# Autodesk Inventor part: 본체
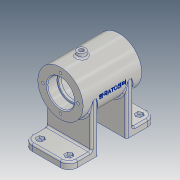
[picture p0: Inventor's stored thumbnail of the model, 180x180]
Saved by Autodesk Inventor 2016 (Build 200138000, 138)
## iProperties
Created: 2017-02
Part Number: 본체
Material: 알루미늄 6061
Document SubType Name: Modeling
Designer: CAMTIC
Density: 2.7 g/cm^3
Appearance: 알루미늄 - 평지
Mass: 355.336 g
Surface Area: 422.271 cm^2
Volume: 131.606 cm^3
Author: CAMTIC
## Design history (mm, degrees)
sketch "스케치1"
  geometry: L1 (-35, 27)-(35, 27); L2 (35, 27)-(35, 0); L3 (35, 0)-(-35, 0); L4 (-35, 0)-(-35, 27); L5 (-52, -52)-(52, -52); L6 (52, -52)-(52, -60); L7 (52, -60)-(-52, -60); L8 (-52, -60)-(-52, -52); L9 (-25, 0)-(-17, 0); L10 (-17, 0)-(-17, -52); L11 (-17, -52)-(-25, -52); L12 (-25, -52)-(-25, 0); L13 (17, 0)-(25, 0); L14 (25, 0)-(25, -52); L15 (25, -52)-(17, -52); L16 (17, -52)-(17, 0); L17 (0, -77.4)-(0, 44.4) reference; 3 further points
  constraints: 32 end point, 8 parallel, 4 horizontal, 4 perpendicular, 2 collinear, 2 midpoint, 2 point on line, 1 coincident, 1 vertical alignment
  dimensions: "d0" = 54 diameter of L1 L3; "d1" = 70 distance between parallel lines of L2 L4; "d2" = 8 distance of L5.end L6.end; "d3" = 104 distance of L6.end L7.end; "d4" = 60 distance from line of L3.end L7; "d5" = 8 distance of L9.start L9.end; "d6" = 8 distance of L13.start L13.end; "d7" = 17 distance from line of point (0, -52) L10; "d8" = 17 distance between parallel lines of L16 L17
revolve "회전1" stored, may be unused: angle "d9" = 90 deg
extrude "돌출1" join sketch "스케치1" stored distance "d10" = 54; taper "d12" = 0 deg; dims "d11" = 5, "d13" = 0
extrude "돌출2" join sketch "스케치1" stored distance "d14" = 54; taper "d15" = 0 deg
sketch "스케치2"
  geometry: L1 (-17, -34.654)-(17, -34.654); L2 (17, -34.654)-(17, -60); L3 (17, -60)-(-17, -60); L4 (-17, -60)-(-17, -34.654); L5 (-35, -27)-(35, -27) reference; L6 (-17, -52)-(-17, 0) reference; L7 (17, 0)-(17, -52) reference; L8 (-52, -60)-(52, -60) reference; 1 further point
  constraints: 8 end point, 3 collinear, 2 parallel, 1 horizontal, 1 perpendicular
  dimensions: "d16" = 25.34558 distance between parallel lines of L3 L1
extrude "돌출3" cut sketch "스케치2" stored distance "d17" = 54; taper "d18" = 0 deg
node "작업 평면1"
sketch "스케치3"
  geometry: L1 (52, -27)-(52, 27) reference; L2 (35, 27)-(35, -27) reference; C1 r 5 at (10, 0); 1 further point
  constraints: 1 centre point, 1 horizontal alignment
  dimensions: "d20" = 10 diameter of C1; "d24" = 25 distance from line of C1.centre L2
extrude "돌출4" join sketch "스케치3" stored distance "d22" = 54; taper "d23" = 0 deg
sketch "스케치4"
  geometry: L1 (-35, -27)-(-35, 27) reference; L2 (-35, 0)-(-23, 0); L3 (-23, 0)-(-23, 16); L4 (-23, 16)-(-35, 16); L5 (-35, 16)-(-35, 0); L6 (-23, 0)-(-20, 0); L7 (-20, 0)-(-20, 14); L8 (-20, 14)-(-23, 14); L9 (-23, 14)-(-23, 0); L10 (-20, 0)-(20, 0); L11 (20, 0)-(20, 22); L12 (20, 22)-(-20, 22); L13 (-20, 22)-(-20, 0); L14 (20, 0)-(23, 0); L15 (23, 0)-(23, 14); L16 (23, 14)-(20, 14); L17 (20, 14)-(20, 0); L18 (23, 0)-(35, 0); L19 (35, 0)-(35, 16); L20 (35, 16)-(23, 16); L21 (23, 16)-(23, 0); L22 (35, -27)-(35, 27) reference; 1 further point
  constraints: 40 end point, 10 parallel, 5 horizontal, 5 perpendicular, 1 collinear, 1 midpoint
  dimensions: "d25" = 12 distance of L3.end L4.end; "d26" = 3 distance of L7.end L8.end; "d27" = 3 distance of L15.end L16.end (= d26); "d28" = 12 distance of L19.end L20.end (= d25); "d29" = 32 diameter of L4 L2; "d30" = 28 diameter of L8 L6; "d31" = 44 diameter of L12 L10; "d32" = 28 diameter of L16 L14; "d33" = 32 diameter of L20 L18
revolve "회전2" sketch "스케치4" stored, may be unused: angle "d34" = 90 deg
fillet "모깎기1" dims "d35" = 3
fillet "모깎기2" dims "d36" = 0.3
chamfer "모따기1" distance "d37" = 1; stored, may be unused: second distance "d38" = 2, angle "d39" = 45 deg
sketch "스케치5"
  geometry: C1 r 5 at (0, 0) reference; 1 further point
hole "구멍1" sketch "스케치5" at (0, 0) diameter "d40" = 5.188; stored, may be unused: countersink angle "d44" = 90 deg, drill point angle "d46" = 0 deg; dims "d41" = 12, "d42" = 4, "d43" = 2, "d45" = 16
fillet "모깎기3" dims "d47" = 2
sketch "스케치6"
  geometry: L1 (0, 0)-(-25.16, -16.339); L2 (0, 0)-(-44.384, 0); C1 r 14 at (0, 0) reference; 1 further point
  constraints: 4 end point, 1 horizontal
  dimensions: "d48" = 30 distance of L1.start L1.end; "d49" = 33 deg angle of L1 L2
node "작업 평면2"
sketch "스케치7"
  geometry: C1 r 6 at (0, 0); 1 further point
  constraints: 1 centre point, 1 coincident
  dimensions: "d50" = 12 diameter of C1
extrude "돌출5" join sketch "스케치7" stored distance "d51" = 54; taper "d52" = 0 deg
sketch "스케치8"
  geometry: C1 r 6 at (0, 0) reference; 2 further points
  constraints: 1 coincident
hole "구멍2" sketch "스케치8" at (0, 0), (0, 0) diameter "d53" = 5.188; stored, may be unused: countersink angle "d57" = 90 deg, drill point angle "d59" = 0 deg; dims "d54" = 12, "d55" = 4, "d56" = 2, "d58" = 16
fillet "모깎기4" dims "d60" = 2
sketch "스케치9" dims "d61" = 42
  geometry: L1 (0, 0)-(0, 21); C1 r 27 at (0, 0) reference; C2 r 14 at (0, 0) reference; 3 further points
  constraints: 2 coincident, 2 end point, 1 vertical, 1 vertical alignment, 2 other
hole "구멍3" sketch "스케치9" at (0, 21) diameter "d62" = 3.242; stored, may be unused: countersink angle "d66" = 90 deg, drill point angle "d68" = 118 deg; dims "d63" = 8, "d64" = 4, "d65" = 2, "d67" = 10
node "작업 평면4"
sketch "스케치10"
  geometry: L1 (-35, 27)-(35, 27) reference; L2 (-35, -27)-(-35, 27) reference; 2 further points
  constraints: 1 coincident, 1 other
  dimensions: "d73" = 27 distance from line of point (0, 0) L1; "d74" = 35 distance from line of point (0, 0) L2 (derived)
feature "엠보싱1" sketch "스케치10" dims "d12" = 0, "d75" = 0.5, "d76" = 0
fillet "모깎기5" dims "d77" = 10
sketch "스케치11"
  geometry: L1 (17, 54)-(-8, 54) reference; L2 (27, 10)-(27, 44) reference; L3 (-25, 64.9)-(-25, -11.401) reference; L4 (19.25, 47.897)-(21.5, 44); L5 (21.5, 44)-(19.25, 40.103); L6 (19.25, 40.103)-(14.75, 40.103); L7 (14.75, 40.103)-(12.5, 44); L8 (12.5, 44)-(14.75, 47.897); L9 (14.75, 47.897)-(19.25, 47.897); L10 (12.5, 44)-(21.5, 44); L11 (14.75, 40.103)-(19.25, 47.897); L12 (19.25, 40.103)-(14.75, 47.897); L13 (19.25, 13.897)-(21.5, 10); L14 (21.5, 10)-(19.25, 6.103); L15 (19.25, 6.103)-(14.75, 6.103); L16 (14.75, 6.103)-(12.5, 10); L17 (12.5, 10)-(14.75, 13.897); L18 (14.75, 13.897)-(19.25, 13.897); L19 (12.5, 10)-(21.5, 10); L20 (14.75, 6.103)-(19.25, 13.897); L21 (19.25, 6.103)-(14.75, 13.897); L22 (-64.75, 13.897)-(-62.5, 10); L23 (-62.5, 10)-(-64.75, 6.103); L24 (-64.75, 6.103)-(-69.25, 6.103); L25 (-69.25, 6.103)-(-71.5, 10); L26 (-71.5, 10)-(-69.25, 13.897); L27 (-69.25, 13.897)-(-64.75, 13.897); L28 (-71.5, 10)-(-62.5, 10); L29 (-69.25, 6.103)-(-64.75, 13.897); L30 (-64.75, 6.103)-(-69.25, 13.897); L31 (-64.75, 47.897)-(-62.5, 44); L32 (-62.5, 44)-(-64.75, 40.103); L33 (-64.75, 40.103)-(-69.25, 40.103); L34 (-69.25, 40.103)-(-71.5, 44); L35 (-71.5, 44)-(-69.25, 47.897); L36 (-69.25, 47.897)-(-64.75, 47.897); L37 (-71.5, 44)-(-62.5, 44); L38 (-69.25, 40.103)-(-64.75, 47.897); L39 (-64.75, 40.103)-(-69.25, 47.897); 16 further points
  constraints: 72 end point, 4 coincident, 4 horizontal, 4 midpoint, 2 symmetric about line, 1 vertical alignment, 52 other
  dimensions: "d78" = 34 distance of point (17, 10) point (17, 44); "d79" = 10 distance from line of L1 point (17, 44); "d80" = 10 distance from line of point (17, 44) L2; "d81" = 9 distance of L7.end L4.end; "d82" = 9 distance of L16.end L13.end; "d83" = 9 distance of L25.end L22.end; "d84" = 9 distance of L34.end L31.end
extrude "돌출6" cut sketch "스케치11" distance "d85" = 3; taper "d86" = 0 deg
sketch "스케치12"
  geometry: L1 (-64.75, 13.897)-(-69.25, 13.897) reference; L2 (-69.25, 13.897)-(-71.5, 10) reference; L3 (-71.5, 10)-(-69.25, 6.103) reference; L4 (-69.25, 6.103)-(-64.75, 6.103) reference; L5 (-64.75, 6.103)-(-62.5, 10) reference; L6 (-62.5, 10)-(-64.75, 13.897) reference; L7 (19.25, 47.897)-(14.75, 47.897) reference; L8 (14.75, 47.897)-(12.5, 44) reference; L9 (12.5, 44)-(14.75, 40.103) reference; L10 (14.75, 40.103)-(19.25, 40.103) reference; L11 (19.25, 40.103)-(21.5, 44) reference; L12 (21.5, 44)-(19.25, 47.897) reference; L13 (19.25, 13.897)-(14.75, 13.897) reference; L14 (14.75, 13.897)-(12.5, 10) reference; L15 (12.5, 10)-(14.75, 6.103) reference; L16 (14.75, 6.103)-(19.25, 6.103) reference; L17 (19.25, 6.103)-(21.5, 10) reference; L18 (21.5, 10)-(19.25, 13.897) reference; L19 (-64.75, 47.897)-(-69.25, 47.897) reference; L20 (-69.25, 47.897)-(-71.5, 44) reference; L21 (-71.5, 44)-(-69.25, 40.103) reference; L22 (-69.25, 40.103)-(-64.75, 40.103) reference; L23 (-64.75, 40.103)-(-62.5, 44) reference; L24 (-62.5, 44)-(-64.75, 47.897) reference; L25 (-67, 54)-(-42, 54) reference; L26 (-42, 54)-(-42, 0) reference; L27 (-42, 0)-(-67, 0) reference; L28 (-77, 10)-(-77, 44) reference; L29 (27, 44)-(27, 10) reference; L30 (17, 0)-(-8, 0) reference; L31 (-8, 0)-(-8, 54) reference; L32 (-8, 54)-(17, 54) reference; A1 r 10 centre (-67, 44) between (-67, 54) and (-77, 44) reference; A2 r 10 centre (-67, 10) between (-77, 10) and (-67, 0) reference; A3 r 10 centre (17, 44) between (27, 44) and (17, 54) reference; A4 r 10 centre (17, 10) between (17, 0) and (27, 10) reference; 1 further point
hole "구멍4" sketch "스케치12" at (17, 44), (17, 10), (-67, 10), (-67, 44) diameter "d87" = 5; stored, may be unused: countersink angle "d91" = 90 deg, drill point angle "d93" = 118 deg; dims "d88" = 8, "d89" = 4, "d90" = 2, "d92" = 10
fillet "모깎기6" dims "d94" = 2
fillet "모깎기7" dims "d95" = 2
fillet "모깎기8" dims "d96" = 2
fillet "모깎기9" dims "d97" = 2
node "솔리드1"
pattern_circular "원형 패턴1" dims angle "d70" = 360 deg
mirror "대칭1"
node "작업 평면3"
node "절단 모서리 투영1"
other parameters: "d19" = 32
